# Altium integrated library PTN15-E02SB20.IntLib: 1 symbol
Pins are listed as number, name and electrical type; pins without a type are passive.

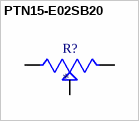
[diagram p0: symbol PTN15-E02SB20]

## PTN15-E02SB20
designator R?
15 mm, 2 kÎ©, Vertical, Linear, Screwdriver Shaftless Trimmer Potentiometer; MF: CUI Devices; MP: PTN15-E02SB20
footprint TRIM_PTN15-E02SB20
pins: 1 INITIAL, 2 WIPER, 3 FINAL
